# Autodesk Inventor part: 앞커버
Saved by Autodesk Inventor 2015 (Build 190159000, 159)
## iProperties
Created: 2025-06
Part Number: 앞커버
Material: 일반
Document SubType Name: Modeling
Designer: User
Density: 1 g/cm^3
Appearance: 기본값
Author: User
Author: jhkim
Creation Date: 2025-05-23
Sending System: Autodesk Inventor 2026
Preprocessor: ST-DEVELOPER v20.1
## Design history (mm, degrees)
node "앞커버1"
node "솔리드1"
node "기준1"
